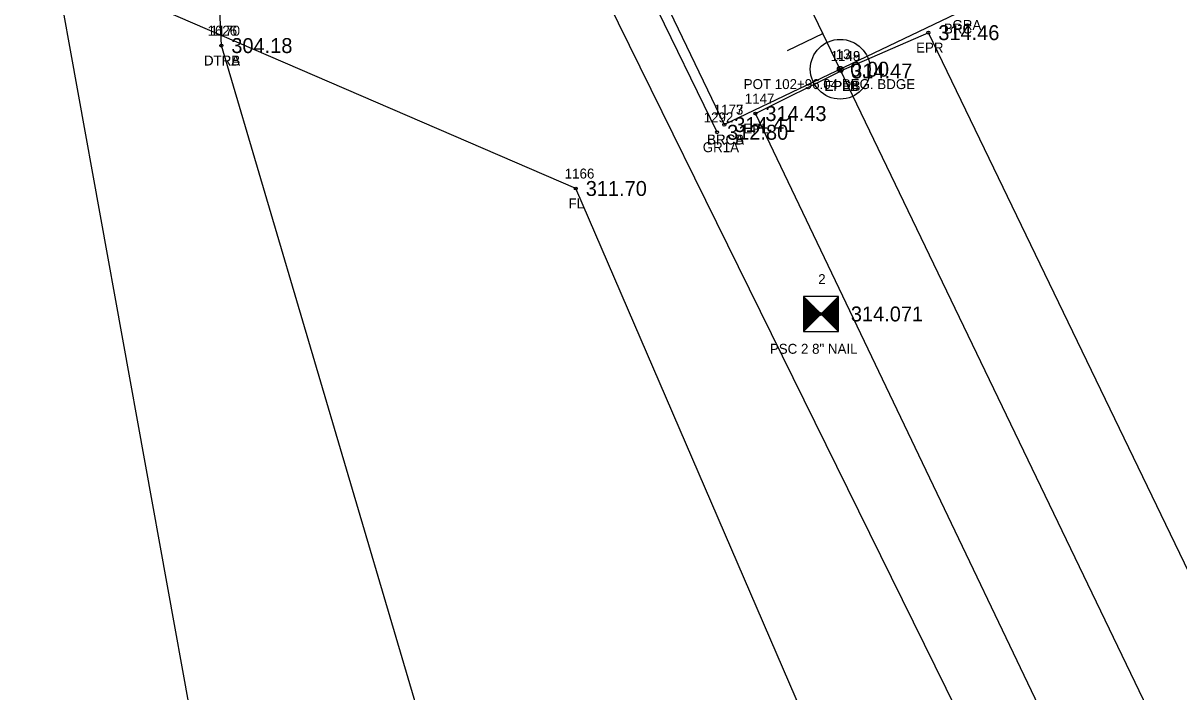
# Model space of a CAD drawing. Extents: x 1865045 to 1867370, y 910391 to 914218.
# Drawn here: x 1866324 to 1866440, y 910971.7 to 911038.9 of the extents above; entities that cross this region are included whole.
import ezdxf

# ---------------------------------------------------------------- set-up
doc = ezdxf.new("R2010")
doc.units = 0
for name, color, linetype in [('RD_EX_Bridge', 7, 'Continuous'), ('RD_EX_Bridge_txCode', 7, 'Continuous'), ('RD_EX_Fence_Other', 7, 'Continuous'), ('RD_EX_Fence_Other_txCode', 7, 'Continuous'), ('RD_EX_GuardRail', 7, 'Continuous'), ('RD_EX_GuardRail_txCode', 7, 'Continuous'), ('RD_EX_H2O', 7, 'Continuous'), ('RD_EX_H2O_txCode', 7, 'Continuous'), ('RD_EX_Road', 7, 'Continuous'), ('RD_EX_Road_txCode', 7, 'Continuous'), ('RD_EX_TX_Bridge_ELEV', 7, 'Continuous'), ('RD_EX_TX_Fence_Other_ELEV', 7, 'Continuous'), ('RD_EX_TX_GuardRail_ELEV', 7, 'Continuous'), ('RD_EX_TX_H2O_ELEV', 7, 'Continuous'), ('RD_EX_TX_Road_ELEV', 7, 'Continuous'), ('RD_EX_VEG', 7, 'Continuous'), ('RD_HC_Cl', 7, 'Continuous'), ('RD_HC_Data', 7, 'Continuous'), ('RD_HC_Data_Tic', 7, 'Continuous'), ('RD_HC_Survey', 7, 'Continuous'), ('RD_HC_Survey_ELEV', 7, 'Continuous'), ('RD_HC_txCode', 7, 'Continuous'), ('RD_SMD_Locator', 7, 'Continuous')]:
    doc.layers.add(name, color=color, linetype=linetype)

msp = doc.modelspace()

# ---------------------------------------------------------------- linework, layer by layer
at = {"layer": 'RD_EX_Bridge'}
msp.add_lwpolyline([(1866394.37, 911028.71), (1866417.68, 911039.86), (1866378.75, 911120.69), (1866355.6, 911109.43), (1866394.37, 911028.71)], dxfattribs=at)
at = {"layer": 'RD_EX_Fence_Other'}
msp.add_lwpolyline([(1866495.48, 910749.21), (1866508.82, 910756.58), (1866493.03, 910785.29), (1866469.81, 910829.93), (1866443.69, 910882.22), (1866422.34, 910922.89), (1866379.46, 911022.29), (1866316.24, 911049.61), (1866298.72, 911056.62), (1866262.33, 911070.09)], dxfattribs=at)
at = {"layer": 'RD_EX_GuardRail'}
msp.add_line((1866393.65, 911027.94), (1866354.28, 911108.94), dxfattribs=at)
at = {"layer": 'RD_EX_H2O'}
for points in [[(1866343.87, 911036.65), (1866342.92, 911057), (1866346.53, 911055.45), (1866387.02, 911048.01), (1866408.72, 911062.1), (1866419.85, 911069.2), (1866443.37, 911096.45)], [(1866349.43, 910920.4), (1866342.95, 910957.57), (1866327.26, 911044.36)], [(1866423.23, 910868.18), (1866404.71, 910916.06), (1866383.72, 910940.15), (1866365.81, 910962.29), (1866343.87, 911036.65)]]:
    msp.add_lwpolyline(points, dxfattribs=at)
at = {"layer": 'RD_EX_Road'}
for points in [[(1866813.99, 910446.88), (1866778.44, 910479.3), (1866742.34, 910514.45), (1866706.87, 910550.71), (1866695.16, 910564.33), (1866672.6, 910589.75), (1866641.04, 910629.03), (1866609.7, 910670.28), (1866582.23, 910711.25), (1866556.44, 910754.58), (1866532.04, 910798.87), (1866507.56, 910846.03), (1866483.5, 910895.43), (1866461.16, 910941.96), (1866414.86, 911037.95), (1866406.11, 911034.1)], [(1866800.58, 910432.45), (1866764.32, 910465.74), (1866727.39, 910500.95), (1866691.9, 910537.68), (1866657.44, 910577.07), (1866624.97, 910617.36), (1866593.69, 910658.89), (1866565.16, 910701.48), (1866538.98, 910745.57), (1866531.34, 910758.5), (1866513.94, 910791.05), (1866489.48, 910838.44), (1866465.73, 910886.02), (1866443.47, 910933.62), (1866397.5, 911029.82), (1866406.11, 911034.1)]]:
    msp.add_lwpolyline(points, dxfattribs=at)
at = {"layer": 'RD_EX_VEG'}
msp.add_lwpolyline([(1866452.86, 910898.44), (1866327.79, 911152.66), (1866304.37, 911199.34), (1866261.27, 911293.31), (1866216.38, 911387.21), (1866171.77, 911477.63), (1866125.33, 911567.24), (1866081.32, 911550.6)], dxfattribs=at)
at = {"layer": 'RD_HC_Cl'}
msp.add_line((1866502.49, 910833.56), (1866280.52, 911295.32), dxfattribs=at)
at = {"layer": 'RD_HC_Data'}
for radius in [3, 0.282]:
    msp.add_circle((1866406.01, 911034.28), radius, dxfattribs=at)
at = {"layer": 'RD_HC_Data_Tic'}
msp.add_line((1866404.29, 911037.85), (1866400.69, 911036.11), dxfattribs=at)
at = {"layer": 'RD_HC_Survey'}
for p, q in [((1866402.33, 911011.43), (1866405.83, 911007.93)), ((1866405.83, 911011.43), (1866402.33, 911007.93)), ((1866402.36, 911011.41), (1866402.36, 911007.96)), ((1866402.38, 911011.38), (1866402.38, 911007.98)), ((1866402.4, 911011.36), (1866402.4, 911008.01)), ((1866402.43, 911011.33), (1866402.43, 911008.03)), ((1866402.45, 911011.31), (1866402.45, 911008.06)), ((1866402.48, 911011.28), (1866402.48, 911008.08)), ((1866402.5, 911011.26), (1866402.5, 911008.1)), ((1866402.53, 911011.23), (1866402.53, 911008.13)), ((1866402.55, 911011.21), (1866402.55, 911008.15)), ((1866402.58, 911011.18), (1866402.58, 911008.18)), ((1866402.6, 911011.16), (1866402.6, 911008.2)), ((1866402.63, 911011.13), (1866402.63, 911008.23)), ((1866402.65, 911011.11), (1866402.65, 911008.25)), ((1866402.68, 911011.09), (1866402.68, 911008.28)), ((1866402.7, 911011.06), (1866402.7, 911008.3)), ((1866402.73, 911011.04), (1866402.73, 911008.33)), ((1866402.75, 911011.01), (1866402.75, 911008.35)), ((1866402.78, 911010.99), (1866402.78, 911008.38)), ((1866402.8, 911010.96), (1866402.8, 911008.4)), ((1866402.83, 911010.94), (1866402.83, 911008.43)), ((1866402.85, 911010.91), (1866402.85, 911008.45)), ((1866402.87, 911010.89), (1866402.87, 911008.48)), ((1866402.9, 911010.86), (1866402.9, 911008.5)), ((1866402.92, 911010.84), (1866402.92, 911008.53)), ((1866402.95, 911010.81), (1866402.95, 911008.55)), ((1866402.97, 911010.79), (1866402.97, 911008.57)), ((1866403, 911010.76), (1866403, 911008.6)), ((1866403.02, 911010.74), (1866403.02, 911008.62)), ((1866403.05, 911010.71), (1866403.05, 911008.65)), ((1866403.07, 911010.69), (1866403.07, 911008.67)), ((1866403.1, 911010.66), (1866403.1, 911008.7)), ((1866403.12, 911010.64), (1866403.12, 911008.72)), ((1866403.15, 911010.61), (1866403.15, 911008.75)), ((1866403.17, 911010.59), (1866403.17, 911008.77)), ((1866403.2, 911010.57), (1866403.2, 911008.8)), ((1866403.22, 911010.54), (1866403.22, 911008.82)), ((1866403.25, 911010.52), (1866403.25, 911008.85)), ((1866403.27, 911010.49), (1866403.27, 911008.87)), ((1866403.3, 911010.47), (1866403.3, 911008.9)), ((1866403.32, 911010.44), (1866403.32, 911008.92)), ((1866403.35, 911010.42), (1866403.35, 911008.95)), ((1866403.37, 911010.39), (1866403.37, 911008.97)), ((1866403.39, 911010.37), (1866403.39, 911009)), ((1866403.42, 911010.34), (1866403.42, 911009.02)), ((1866404.74, 911010.34), (1866404.74, 911009.02)), ((1866404.77, 911010.37), (1866404.77, 911009)), ((1866404.79, 911010.39), (1866404.79, 911008.97)), ((1866404.82, 911010.42), (1866404.82, 911008.95)), ((1866404.84, 911010.44), (1866404.84, 911008.92)), ((1866404.87, 911010.47), (1866404.87, 911008.9)), ((1866404.89, 911010.49), (1866404.89, 911008.87)), ((1866404.91, 911010.52), (1866404.91, 911008.85)), ((1866404.94, 911010.54), (1866404.94, 911008.82)), ((1866404.96, 911010.57), (1866404.96, 911008.8)), ((1866404.99, 911010.59), (1866404.99, 911008.77)), ((1866405.01, 911010.61), (1866405.01, 911008.75)), ((1866405.04, 911010.64), (1866405.04, 911008.72)), ((1866405.06, 911010.66), (1866405.06, 911008.7)), ((1866405.09, 911010.69), (1866405.09, 911008.67)), ((1866405.11, 911010.71), (1866405.11, 911008.65)), ((1866405.14, 911010.74), (1866405.14, 911008.62)), ((1866405.16, 911010.76), (1866405.16, 911008.6)), ((1866405.19, 911010.79), (1866405.19, 911008.57)), ((1866405.21, 911010.81), (1866405.21, 911008.55)), ((1866405.24, 911010.84), (1866405.24, 911008.53)), ((1866405.26, 911010.86), (1866405.26, 911008.5)), ((1866405.29, 911010.89), (1866405.29, 911008.48)), ((1866405.31, 911010.91), (1866405.31, 911008.45)), ((1866405.34, 911010.94), (1866405.34, 911008.43)), ((1866405.36, 911010.96), (1866405.36, 911008.4)), ((1866405.38, 911010.99), (1866405.38, 911008.38)), ((1866405.41, 911011.01), (1866405.41, 911008.35)), ((1866405.43, 911011.04), (1866405.43, 911008.33)), ((1866405.46, 911011.06), (1866405.46, 911008.3)), ((1866405.48, 911011.09), (1866405.48, 911008.28)), ((1866405.51, 911011.11), (1866405.51, 911008.25)), ((1866405.53, 911011.13), (1866405.53, 911008.23)), ((1866405.56, 911011.16), (1866405.56, 911008.2)), ((1866405.58, 911011.18), (1866405.58, 911008.18)), ((1866405.61, 911011.21), (1866405.61, 911008.15)), ((1866405.63, 911011.23), (1866405.63, 911008.13)), ((1866405.66, 911011.26), (1866405.66, 911008.1)), ((1866405.68, 911011.28), (1866405.68, 911008.08)), ((1866405.71, 911011.31), (1866405.71, 911008.06)), ((1866405.73, 911011.33), (1866405.73, 911008.03)), ((1866405.76, 911011.36), (1866405.76, 911008.01)), ((1866405.78, 911011.38), (1866405.78, 911007.98)), ((1866405.81, 911011.41), (1866405.81, 911007.96)), ((1866403.44, 911010.32), (1866403.44, 911009.05)), ((1866403.47, 911010.29), (1866403.47, 911009.07)), ((1866403.49, 911010.27), (1866403.49, 911009.09)), ((1866403.52, 911010.24), (1866403.52, 911009.12)), ((1866403.54, 911010.22), (1866403.54, 911009.14)), ((1866403.57, 911010.19), (1866403.57, 911009.17)), ((1866403.59, 911010.17), (1866403.59, 911009.19)), ((1866403.62, 911010.14), (1866403.62, 911009.22)), ((1866403.64, 911010.12), (1866403.64, 911009.24)), ((1866403.67, 911010.1), (1866403.67, 911009.27)), ((1866403.69, 911010.07), (1866403.69, 911009.29)), ((1866403.72, 911010.05), (1866403.72, 911009.32)), ((1866403.74, 911010.02), (1866403.74, 911009.34)), ((1866403.77, 911010), (1866403.77, 911009.37)), ((1866403.79, 911009.97), (1866403.79, 911009.39)), ((1866403.82, 911009.95), (1866403.82, 911009.42)), ((1866403.84, 911009.92), (1866403.84, 911009.44)), ((1866403.86, 911009.9), (1866403.86, 911009.47)), ((1866403.89, 911009.87), (1866403.89, 911009.49)), ((1866403.91, 911009.85), (1866403.91, 911009.52)), ((1866403.94, 911009.82), (1866403.94, 911009.54)), ((1866403.96, 911009.8), (1866403.96, 911009.56)), ((1866403.99, 911009.77), (1866403.99, 911009.59)), ((1866404.01, 911009.75), (1866404.01, 911009.61)), ((1866404.04, 911009.72), (1866404.04, 911009.64)), ((1866404.06, 911009.7), (1866404.06, 911009.66)), ((1866404.1, 911009.7), (1866404.1, 911009.66)), ((1866404.12, 911009.72), (1866404.12, 911009.64)), ((1866404.15, 911009.75), (1866404.15, 911009.61)), ((1866404.17, 911009.77), (1866404.17, 911009.59)), ((1866404.2, 911009.8), (1866404.2, 911009.56)), ((1866404.22, 911009.82), (1866404.22, 911009.54)), ((1866404.25, 911009.85), (1866404.25, 911009.52)), ((1866404.27, 911009.87), (1866404.27, 911009.49)), ((1866404.3, 911009.9), (1866404.3, 911009.47)), ((1866404.32, 911009.92), (1866404.32, 911009.44)), ((1866404.35, 911009.95), (1866404.35, 911009.42)), ((1866404.37, 911009.97), (1866404.37, 911009.39)), ((1866404.39, 911010), (1866404.39, 911009.37)), ((1866404.42, 911010.02), (1866404.42, 911009.34)), ((1866404.44, 911010.05), (1866404.44, 911009.32)), ((1866404.47, 911010.07), (1866404.47, 911009.29)), ((1866404.49, 911010.1), (1866404.49, 911009.27)), ((1866404.52, 911010.12), (1866404.52, 911009.24)), ((1866404.54, 911010.14), (1866404.54, 911009.22)), ((1866404.57, 911010.17), (1866404.57, 911009.19)), ((1866404.59, 911010.19), (1866404.59, 911009.17)), ((1866404.62, 911010.22), (1866404.62, 911009.14)), ((1866404.64, 911010.24), (1866404.64, 911009.12)), ((1866404.67, 911010.27), (1866404.67, 911009.09)), ((1866404.69, 911010.29), (1866404.69, 911009.07)), ((1866404.72, 911010.32), (1866404.72, 911009.05))]:
    msp.add_line(p, q, dxfattribs=at)
msp.add_lwpolyline([(1866405.83, 911011.43), (1866402.33, 911011.43), (1866402.33, 911007.93), (1866405.83, 911007.93)], close=True, dxfattribs=at)
at = {"layer": 'RD_SMD_Locator'}
for centre in [(1866414.86, 911037.95), (1866343.87, 911036.65), (1866343.87, 911036.65), (1866406.01, 911034.28), (1866406.11, 911034.1), (1866406.11, 911034.1), (1866397.5, 911029.82), (1866393.65, 911027.94), (1866394.37, 911028.71), (1866394.37, 911028.71), (1866379.46, 911022.29), (1866404.08, 911009.68)]:
    msp.add_circle(centre, 0.15, dxfattribs=at)

# ---------------------------------------------------------------- texts
at = {"layer": 'RD_EX_Bridge_txCode'}
for s, p in [('BRC', (1866416.43, 911037.86)), ('1173', (1866393.31, 911029.71)), ('1177', (1866393.31, 911029.71)), ('BRCA', (1866392.63, 911026.71)), ('BRCB', (1866392.65, 911026.71))]:
    msp.add_text(s, height=1, dxfattribs=at).set_placement(p)
at = {"layer": 'RD_EX_Fence_Other_txCode'}
for s, p in [('1166', (1866378.35, 911023.29)), ('FL', (1866378.73, 911020.29))]:
    msp.add_text(s, height=1, dxfattribs=at).set_placement(p)
at = {"layer": 'RD_EX_GuardRail_txCode'}
for s, p in [('GRA', (1866417.28, 911038.22)), ('1292', (1866392.3, 911028.94)), ('GR1A', (1866392.21, 911025.94))]:
    msp.add_text(s, height=1, dxfattribs=at).set_placement(p)
at = {"layer": 'RD_EX_H2O_txCode'}
for s, p in [('1626', (1866342.48, 911037.65)), ('1170', (1866342.77, 911037.65)), ('DTRA', (1866342.11, 911034.65)), ('DTRB', (1866342.13, 911034.65))]:
    msp.add_text(s, height=1, dxfattribs=at).set_placement(p)
at = {"layer": 'RD_EX_Road_txCode'}
for s, p in [('1148', (1866405.05, 911035.1)), ('1149', (1866405.05, 911035.1)), ('EPR', (1866413.63, 911035.95)), ('EPRB', (1866404.41, 911032.1)), ('EPLB', (1866404.44, 911032.1)), ('1147', (1866396.43, 911030.82)), ('EPL', (1866396.29, 911027.82))]:
    msp.add_text(s, height=1, dxfattribs=at).set_placement(p)
at = {"layer": 'RD_EX_TX_Bridge_ELEV'}
msp.add_text('314.41', height=1.5, dxfattribs=at).set_placement((1866395.37, 911027.96))
msp.add_text('314.41', height=1.5, dxfattribs=at).set_placement((1866395.37, 911027.96))
at = {"layer": 'RD_EX_TX_Fence_Other_ELEV'}
msp.add_text('311.70', height=1.5, dxfattribs=at).set_placement((1866380.46, 911021.54))
at = {"layer": 'RD_EX_TX_GuardRail_ELEV'}
msp.add_text('312.80', height=1.5, dxfattribs=at).set_placement((1866394.65, 911027.19))
at = {"layer": 'RD_EX_TX_H2O_ELEV'}
msp.add_text('304.18', height=1.5, dxfattribs=at).set_placement((1866344.87, 911035.9))
msp.add_text('304.18', height=1.5, dxfattribs=at).set_placement((1866344.87, 911035.9))
at = {"layer": 'RD_EX_TX_Road_ELEV'}
for s, p in [('314.46', (1866415.86, 911037.2)), ('314.47', (1866407.11, 911033.35)), ('314.47', (1866407.11, 911033.35)), ('314.43', (1866398.5, 911029.07))]:
    msp.add_text(s, height=1.5, dxfattribs=at).set_placement(p)
at = {"layer": 'RD_HC_Survey_ELEV'}
for s, p in [('0.00', (1866407.01, 911033.53)), ('314.071', (1866407.08, 911008.93))]:
    msp.add_text(s, height=1.5, dxfattribs=at).set_placement(p)
at = {"layer": 'RD_HC_txCode'}
for s, p in [('13', (1866405.56, 911035.28)), ('POT 102+96.04 BEG. BDGE', (1866396.32, 911032.28)), ('2', (1866403.8, 911012.68)), ('PSC 2 8" NAIL', (1866398.95, 911005.68))]:
    msp.add_text(s, height=1, dxfattribs=at).set_placement(p)

doc.saveas('drawing.dxf')
